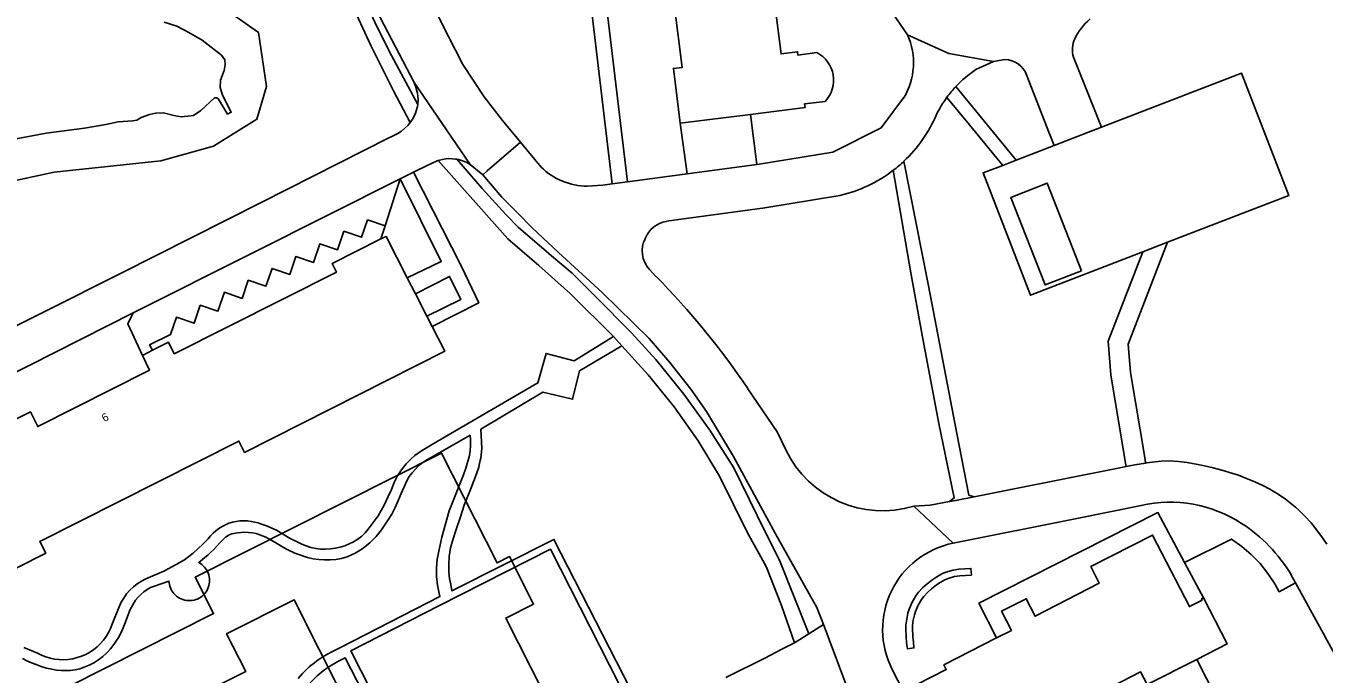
# Model space of a CAD drawing. Extents: x 158132 to 159658, y 385257 to 387209.
# Drawn here: x 159064.7 to 159226.8, y 386381.6 to 386462.6 of the extents above; entities that cross this region are included whole.
import ezdxf

# ---------------------------------------------------------------- set-up
doc = ezdxf.new("R2010")
doc.units = 0
for name, color, linetype in [('IMGEO_Groenvoorziening', 7, 'Continuous'), ('IMGEO_Meer_plas_ven_vijver', 7, 'Continuous'), ('IMGEO_Pand', 7, 'Continuous'), ('IMGEO_Pand_nummerreeks', 7, 'Continuous'), ('IMGEO_Pand_vergunning_verleend', 7, 'Continuous'), ('IMGEO_Parkeervlak_open', 7, 'Continuous'), ('IMGEO_Rijbaan_lokaal_gesloten', 7, 'Continuous'), ('IMGEO_Rijbaan_lokaal_open', 7, 'Continuous'), ('IMGEO_Voetpad_open', 7, 'Continuous')]:
    doc.layers.add(name, color=color, linetype=linetype)

msp = doc.modelspace()

# ---------------------------------------------------------------- linework, layer by layer
at = {"layer": 'IMGEO_Groenvoorziening'}
for points in [[(159088.96, 386465.12), (159093.72, 386461.76), (159094.7, 386455.04), (159093.51, 386450.93), (159088.09, 386447.57), (159081.49, 386445.73), (159068.17, 386444.32), (159059.08, 386442.37), (159042.9, 386435.88), (159037.76, 386432.56), (159020.21, 386419.95), (159017.17, 386418.5), (159014.2, 386417.9), (159011.48, 386417.94), (159008.93, 386418.79), (159006.56, 386420.41), (159001.86, 386425.64), (159000.77, 386428.72), (159000.8, 386431.97), (159002.13, 386435.24), (159005.17, 386440.01), (159011.8, 386444.98), (159020.33, 386450.04)], [(159109.52, 386437.62), (159109, 386435.97)]]:
    msp.add_lwpolyline(points, dxfattribs=at)
at = {"layer": 'IMGEO_Meer_plas_ven_vijver'}
msp.add_lwpolyline([(159081.92, 386463.07), (159083.53, 386462.57), (159085.02, 386461.77), (159086.68, 386460.82), (159088.16, 386459.66), (159089.1, 386458.94), (159089.5, 386458.35), (159089.55, 386457.77), (159089.41, 386457.01), (159088.96, 386455.8), (159088.92, 386454.9), (159089.23, 386453.96), (159090.31, 386451.8), (159089.86, 386451.58), (159088.73, 386453.44), (159088.49, 386453.63), (159088.22, 386453.61), (159086.52, 386452.04), (159085.6, 386451.41), (159084.87, 386451.31), (159084.07, 386451.25), (159083.15, 386451.41), (159081.84, 386451.74), (159080.84, 386451.69), (159080.1, 386451.52), (159079.07, 386451.14), (159078.52, 386450.8), (159078, 386450.75), (159076.16, 386450.61), (159074.66, 386450.28), (159071.97, 386449.81), (159067.17, 386449.18), (159061.17, 386448.08)], dxfattribs=at)
at = {"layer": 'IMGEO_Pand'}
for points in [[(159155.5, 386521.58), (159153.11, 386521.28), (159153.08, 386521.47), (159137.7, 386519.52), (159138.58, 386512.59), (159139.52, 386512.71), (159141.14, 386500), (159141.53, 386496.9), (159143.04, 386497.09), (159143.74, 386491.82), (159135.51, 386490.77), (159137.19, 386477.61), (159145.42, 386478.66), (159146.15, 386473.48), (159144.64, 386473.29), (159146.66, 386457.42), (159145.54, 386457.28), (159146.41, 386450.43)], [(159163.46, 386459.26), (159161.1, 386458.96), (159161.05, 386459.36), (159158.99, 386459.1), (159156.22, 386480.84), (159157.42, 386480.99), (159156.91, 386485.02), (159156.46, 386488.53), (159155.92, 386492.83), (159154.68, 386492.67), (159153.74, 386500), (159151.92, 386514.32), (159153.96, 386514.58), (159153.92, 386514.96), (159156.38, 386515.26)], [(159155.18, 386451.54), (159161.99, 386452.41), (159161.94, 386452.84), (159164.51, 386453.16)], [(159146.41, 386450.43), (159155.18, 386451.54)], [(159196.52, 386431.98), (159191.99, 386430.22), (159187.72, 386441.17), (159192.24, 386442.94), (159196.52, 386431.98)], [(159080.46, 386422.06), (159082.45, 386423.06), (159083.18, 386421.62), (159103.45, 386431.83), (159102.91, 386432.89), (159109, 386435.97)], [(159109, 386435.97), (159109.65, 386436.3), (159112.3, 386431.12)], [(159113.33, 386429.1), (159112.3, 386431.12)], [(159114.74, 386426.33), (159113.33, 386429.1)], [(159115.41, 386425.03), (159114.74, 386426.33)], [(159115.41, 386425.03), (159116.99, 386421.94), (159091.98, 386409.3), (159091.27, 386410.7), (159066.39, 386398.16), (159067.13, 386396.71), (159042.48, 386384.25), (159040.85, 386387.48)], [(159079.2, 386421.42), (159080.46, 386422.06)], [(159061.96, 386412.72), (159065.21, 386414.36), (159066.14, 386412.52), (159080.11, 386419.58), (159079.2, 386421.42)], [(159185.93, 386386.11), (159187.77, 386387.04), (159186.54, 386389.44), (159189.62, 386391), (159190.72, 386388.81), (159198.75, 386392.96), (159197.68, 386395.02), (159205.41, 386398.97), (159210.02, 386390.03), (159211.59, 386390.83), (159211.53, 386391.01), (159211.78, 386391.13)], [(159210.92, 386383.43), (159214.72, 386385.36), (159211.78, 386391.13)], [(159175.96, 386380.29), (159179.63, 386382.15), (159179.33, 386382.74), (159185.93, 386386.11)], [(159210.92, 386383.43), (159204.73, 386380.28), (159203.91, 386381.85), (159184.82, 386371.98), (159185.58, 386370.5), (159181.91, 386368.63)]]:
    msp.add_lwpolyline(points, dxfattribs=at)
msp.add_arc((159161.68, 386455.82), 3.88, 316.8175, 62.6095, dxfattribs=at)
at = {"layer": 'IMGEO_Pand_vergunning_verleend'}
msp.add_lwpolyline([(159050.57, 386368.04), (159057.32, 386371.44), (159056.43, 386373.19), (159088.1, 386389.15), (159085.8, 386393.7), (159116.59, 386409.22), (159123.52, 386395.49), (159125.08, 386396.27), (159128.07, 386390.33), (159124.61, 386388.59), (159130.93, 386376.07), (159110.74, 386365.89), (159098.15, 386390.88), (159089.73, 386386.63), (159092.11, 386381.91), (159085.18, 386378.43), (159091.59, 386365.71), (159079.32, 386359.4), (159081.2, 386355.82), (159075.09, 386353.07), (159074.31, 386354.62), (159060.77, 386347.79), (159050.57, 386368.04)], dxfattribs=at)
at = {"layer": 'IMGEO_Parkeervlak_open'}
for points in [[(159199.04, 386449.93), (159216.52, 386456.68), (159222.42, 386441.4), (159207.29, 386435.56)], [(159193.11, 386447.64), (159188.37, 386445.81)], [(159186.69, 386445.16), (159184.24, 386444.22), (159190.15, 386428.93), (159204.18, 386434.35)], [(159111.4, 386443.47), (159109.52, 386437.62)], [(159080.46, 386422.06), (159080.11, 386422.73), (159082.72, 386424.03), (159083.46, 386426.19), (159085.66, 386425.44), (159086.43, 386427.69), (159088.64, 386426.94), (159089.45, 386429.31), (159091.66, 386428.55), (159092.43, 386430.81), (159094.64, 386430.06), (159095.41, 386432.3), (159097.62, 386431.54), (159098.38, 386433.78), (159100.59, 386433.03), (159101.39, 386435.37), (159103.6, 386434.62), (159104.39, 386436.93), (159106.6, 386436.18), (159107.34, 386438.35), (159107.35, 386438.36), (159109.52, 386437.62)]]:
    msp.add_lwpolyline(points, dxfattribs=at)
at = {"layer": 'IMGEO_Rijbaan_lokaal_gesloten'}
for points in [[(159168.9, 386468.32), (159172.42, 386464.95), (159174.8, 386461.48)], [(159174.8, 386461.48), (159179.96, 386459.17), (159185.54, 386458.14)], [(159183.33, 386457.14), (159185.54, 386458.14)], [(159185.54, 386458.14), (159186.96, 386458.39)], [(159195.54, 386458.71), (159199.04, 386449.93)], [(159189.67, 386456.48), (159192.53, 386449.13), (159193.11, 386447.64)], [(159174.31, 386453.59), (159171.51, 386449.85), (159165.45, 386446.82), (159156.24, 386445.32), (159155.98, 386445.28)], [(159199.04, 386449.93), (159197.4, 386449.3), (159193.11, 386447.64)], [(159126.43, 386448.09), (159122.28, 386444.49), (159121.72, 386444)], [(159129.03, 386444.96), (159126.43, 386448.09)], [(159155.98, 386445.28), (159147.26, 386444.12)], [(159121.72, 386444), (159124.12, 386441.2), (159126.02, 386439.29), (159127.9, 386437.35), (159131.19, 386434.28), (159136.63, 386429.28), (159142.5, 386423.55), (159145.08, 386420.52), (159147.72, 386417.19), (159149.66, 386414.41), (159153.06, 386408.77), (159158.02, 386399.66), (159158.3, 386399.13), (159163.48, 386389.93), (159164.3, 386387.8)], [(159139.8, 386443.12), (159137.91, 386442.87)], [(159147.26, 386444.12), (159139.8, 386443.12)], [(159137.91, 386442.87), (159136.74, 386442.71), (159134.79, 386442.58)], [(159144.68, 386438.18), (159156.97, 386439.87), (159166.34, 386441.4)], [(159143.37, 386431.29), (159142.57, 386432.17)], [(159159.6, 386409.6), (159158.5, 386411.85), (159154.85, 386417.26)], [(159180.51, 386397.96), (159175.58, 386402.58)], [(159160.68, 386385.48), (159162.48, 386386.63)], [(159162.48, 386386.63), (159164.3, 386387.8)], [(159164.3, 386387.8), (159168.14, 386377.56)], [(159160.68, 386385.48), (159159.1, 386384.71), (159156.98, 386383.59), (159152.1, 386381.17)], [(159174.28, 386379.43), (159172.88, 386382.17)]]:
    msp.add_lwpolyline(points, dxfattribs=at)
for centre, radius, start, end in [((159202.49, 386457.69), 7.56, 130.1649, 154.13), ((159166.99, 386458.01), 8.55, 328.8485, 23.9455), ((159198.44, 386459.66), 3.05, 154.2235, 198.2419), ((159186.87, 386455.39), 3, 21.3107, 88.289), ((159191.34, 386445.19), 14.39, 123.8165, 136.9206), ((159191.41, 386445.14), 14.47, 136.9878, 143.8973), ((159191.35, 386445.2), 14.4, 143.9376, 153.9311), ((159162.42, 386458.35), 17.39, 313.3149, 336.8992), ((159134.78, 386450.73), 8.15, 225.1221, 270.0585), ((159162.38, 386458.39), 17.45, 307.5493, 313.3359), ((159162.41, 386458.34), 17.39, 283.0538, 307.5485), ((159145.18, 386434.85), 3.36, 98.6958, 159.2412), ((159144.93, 386434.47), 3.29, 151.3825, 224.3061), ((159073.64, 386362.54), 97.93, 33.976, 44.593), ((159171.67, 386415.39), 13.39, 205.6112, 286.9345), ((159182.68, 386387.17), 11, 101.3473, 207.0455)]:
    msp.add_arc(centre, radius, start, end, dxfattribs=at)
at = {"layer": 'IMGEO_Rijbaan_lokaal_open'}
for points in [[(159113.14, 386455.52), (159108.94, 386463.56), (159106.64, 386468.87), (159104.74, 386473.72), (159103.08, 386479.14)], [(159109.67, 386479.93), (159110.05, 386478.53), (159111.67, 386473.93), (159114, 386468.46), (159116.52, 386463.07), (159119.22, 386457.77), (159121.92, 386453.72), (159124.19, 386450.76), (159126.43, 386448.09)], [(159120.17, 386445.26), (159113.14, 386455.52)], [(159113.14, 386455.52), (159113.35, 386454.95), (159113.51, 386454.48), (159113.56, 386454.21), (159113.61, 386453.88), (159113.67, 386453.37), (159113.63, 386452.88), (159113.61, 386452.78)], [(159113.61, 386452.78), (159113.58, 386452.52), (159113.47, 386452.1), (159113.33, 386451.7), (159113.16, 386451.3), (159112.95, 386450.93), (159112.67, 386450.53)], [(159057.35, 386422.06), (159076.55, 386431.69), (159094.11, 386440.59), (159110.07, 386448.64), (159110.2, 386448.7), (159111.12, 386449.17), (159111.56, 386449.46), (159111.98, 386449.8), (159112.36, 386450.17), (159112.67, 386450.53)], [(159113.09, 386444.32), (159114.87, 386445.21), (159115.95, 386445.69), (159116.05, 386445.73), (159116.15, 386445.76)], [(159116.15, 386445.76), (159116.33, 386445.82), (159116.71, 386445.92), (159117.11, 386445.98), (159117.51, 386446.01), (159117.91, 386446), (159118.31, 386445.96), (159118.49, 386445.93)], [(159118.49, 386445.93), (159118.59, 386445.91), (159118.7, 386445.89), (159119.09, 386445.78), (159119.46, 386445.64), (159119.82, 386445.47), (159120.17, 386445.26)], [(159121.72, 386444), (159120.17, 386445.26)], [(159078.04, 386426.72), (159093.07, 386434.3), (159111.4, 386443.47)], [(159111.4, 386443.47), (159113.09, 386444.32)], [(159061.77, 386418.51), (159078.04, 386426.72)], [(159202.11, 386407.52), (159200.89, 386407.28), (159187.68, 386404.66), (159183.1, 386403.74)], [(159204.54, 386407.96), (159203.19, 386407.73), (159202.11, 386407.52)], [(159204.54, 386407.96), (159204.71, 386407.98), (159205.36, 386408.08), (159206.46, 386408.19), (159207.52, 386408.23), (159208.65, 386408.17), (159209.74, 386408.03), (159211.07, 386407.78), (159211.9, 386407.61), (159212.97, 386407.36), (159214.04, 386407.08), (159215.43, 386406.66), (159216.13, 386406.43), (159217.16, 386406.05), (159218.18, 386405.62), (159219.18, 386405.16), (159220.07, 386404.69), (159221.09, 386404.08), (159222, 386403.46), (159223.28, 386402.45), (159223.7, 386402.07), (159224.49, 386401.3), (159225.23, 386400.48), (159225.69, 386399.92), (159226.65, 386398.61), (159227.16, 386397.82)], [(159175.58, 386402.58), (159177.61, 386402.68), (159180.04, 386403.14)], [(159183.1, 386403.74), (159180.78, 386403.27), (159180.04, 386403.14)], [(159180.51, 386397.96), (159195.93, 386401.05), (159203.97, 386402.67)], [(159222.7, 386394.02), (159223.26, 386393)], [(159223.26, 386393), (159236, 386369.77)]]:
    msp.add_lwpolyline(points, dxfattribs=at)
for centre, radius, start, end in [((159207.6, 386386.79), 16.29, 56.7454, 102.8562), ((159205.89, 386383.96), 19.6, 30.8976, 57.1149)]:
    msp.add_arc(centre, radius, start, end, dxfattribs=at)
at = {"layer": 'IMGEO_Voetpad_open'}
for points in [[(159139.8, 386443.12), (159130.94, 386517.43)], [(159112.67, 386450.53), (159110.57, 386454.48), (159107.78, 386460.06), (159105.15, 386465.72), (159102.7, 386471.45), (159101.94, 386473.64), (159099.08, 386483.66), (159095.79, 386495.63)], [(159137.91, 386442.87), (159133.51, 386479.83), (159133.13, 386479.84), (159132.76, 386479.89), (159132.39, 386479.96), (159132.04, 386480.08), (159131.69, 386480.22), (159131.36, 386480.39), (159131.05, 386480.59), (159130.75, 386480.82), (159130.48, 386481.08), (159130.23, 386481.35), (159130.01, 386481.66), (159129.81, 386481.98), (159129.64, 386482.31), (159109.67, 386479.93)], [(159103.08, 386479.14), (159102.22, 386478.95), (159104.26, 386472.38), (159106.78, 386466.27), (159108.25, 386463.08), (159110.04, 386459.45), (159113.61, 386452.78)], [(159180.83, 386455.02), (159188.37, 386445.81)], [(159186.69, 386445.16), (159182.54, 386450.22), (159179.71, 386453.67)], [(159155.98, 386445.28), (159155.18, 386451.54)], [(159146.41, 386450.43), (159147.26, 386444.12)], [(159116.15, 386445.76), (159124.87, 386435.99), (159128.73, 386432.67), (159132.68, 386429.11), (159138.05, 386423.77)], [(159162.48, 386386.63), (159158.89, 386395.6), (159156.01, 386401.41), (159153.08, 386407.38), (159150.09, 386412.07), (159146.84, 386416.59), (159143.34, 386420.92), (159140.3, 386424.26), (159135.82, 386428.79), (159132.89, 386431.69), (159130.31, 386433.87), (159129.98, 386434.15), (159126.16, 386437.44), (159124.62, 386439.03), (159121.65, 386442.26), (159118.49, 386445.93)], [(159183.1, 386403.74), (159182.45, 386403.97), (159180.96, 386411.67), (159177.42, 386430.11), (159174.35, 386445.69)], [(159188.37, 386445.81), (159186.69, 386445.16)], [(159112.3, 386431.12), (159116.54, 386433.17), (159111.4, 386443.47)], [(159113.09, 386444.32), (159119.08, 386432.55), (159121.23, 386428), (159115.41, 386425.03)], [(159180.04, 386403.14), (159180.63, 386403.6), (159178.71, 386412.89), (159176.69, 386423.48), (159175.2, 386431.73), (159173.01, 386444.55)], [(159207.29, 386435.56), (159202.35, 386422.83), (159202.64, 386419.3), (159204.47, 386408.4), (159204.54, 386407.96)], [(159204.18, 386434.35), (159207.29, 386435.56)], [(159202.11, 386407.52), (159202.04, 386407.94), (159201.92, 386408.71), (159200.19, 386418.99), (159199.84, 386423.2), (159204.18, 386434.35)], [(159114.74, 386426.33), (159118.97, 386428.4), (159117.58, 386431.3), (159113.33, 386429.1)], [(159078.04, 386426.72), (159077.37, 386425.36), (159079.2, 386421.42)], [(159064.39, 386384.92), (159066.1, 386384.21), (159066.61, 386383.96), (159067.14, 386383.75), (159067.69, 386383.59), (159068.24, 386383.47), (159068.81, 386383.41), (159069.38, 386383.39), (159069.95, 386383.43), (159070.51, 386383.51), (159071.07, 386383.65), (159071.61, 386383.83), (159072.13, 386384.05), (159072.63, 386384.33), (159073.11, 386384.64), (159073.55, 386385), (159073.97, 386385.39), (159074.34, 386385.82), (159074.68, 386386.28), (159074.98, 386386.77), (159075.23, 386387.28), (159075.44, 386387.81), (159076.3, 386390), (159076.56, 386390.56), (159076.87, 386391.09), (159077.23, 386391.6), (159077.64, 386392.06), (159078.08, 386392.49), (159078.56, 386392.88), (159079.08, 386393.22), (159079.62, 386393.51), (159081.87, 386394.47), (159083.43, 386395.27), (159084.48, 386395.87), (159085.55, 386396.72), (159086.77, 386397.83), (159087.42, 386398.48), (159087.71, 386398.85), (159088.03, 386399.2), (159088.38, 386399.51), (159088.76, 386399.79), (159089.16, 386400.04), (159089.58, 386400.25), (159090.02, 386400.43), (159090.46, 386400.57), (159090.93, 386400.67), (159091.39, 386400.73), (159091.86, 386400.75), (159092.33, 386400.73), (159092.8, 386400.67), (159093.26, 386400.57), (159093.68, 386400.48), (159094.09, 386400.34), (159094.71, 386400.11), (159095.96, 386399.56), (159097.66, 386398.52), (159098.56, 386398.1), (159099.11, 386397.82), (159099.68, 386397.6), (159100.26, 386397.42), (159100.86, 386397.29), (159101.47, 386397.22), (159102.08, 386397.2), (159102.7, 386397.23), (159103.3, 386397.31), (159103.9, 386397.44), (159104.49, 386397.62), (159105.05, 386397.85), (159105.6, 386398.13), (159106.12, 386398.45), (159106.61, 386398.82), (159107.04, 386399.25), (159107.41, 386399.7), (159107.92, 386400.36), (159108.66, 386401.36), (159109.42, 386402.72), (159109.93, 386403.79), (159110.31, 386404.65), (159110.55, 386405.21), (159110.65, 386405.53), (159111.07, 386406.35), (159111.57, 386407.12), (159112.14, 386407.85), (159112.78, 386408.51), (159113.23, 386408.92), (159113.95, 386409.41), (159115.12, 386410.12), (159116.76, 386411.07), (159128.6, 386417.97), (159129.63, 386421.66), (159133.16, 386420.73), (159138.05, 386423.77)], [(159138.05, 386423.77), (159139.11, 386422.6)], [(159140.13, 386379.79), (159130.62, 386398.42), (159117.87, 386391.99), (159117.73, 386392.77), (159117.59, 386393.53), (159117.47, 386394.31), (159117.48, 386395.28), (159117.54, 386396.3), (159117.71, 386397.35), (159117.98, 386398.36), (159118.36, 386399.54), (159118.95, 386401.26), (159119.42, 386402.7), (159120.29, 386404.87), (159120.94, 386406.6), (159121.23, 386407.44), (159121.34, 386407.9), (159121.42, 386408.28), (159121.48, 386408.59), (159121.55, 386408.95), (159121.59, 386409.42), (159121.61, 386409.78), (159121.47, 386412.18), (159129.24, 386416.83), (159132.95, 386415.93), (159133.82, 386419.51), (159139.11, 386422.6)], [(159139.11, 386422.6), (159142.39, 386419.01), (159145.65, 386414.99), (159148.62, 386410.76), (159151.3, 386406.33), (159154.78, 386399.32), (159157.15, 386395.04), (159159.06, 386390.17), (159160.68, 386385.48)], [(159086.99, 386396.15), (159087.37, 386396.46), (159087.73, 386396.78), (159088.08, 386397.11), (159088.47, 386397.53), (159088.86, 386397.95), (159089.26, 386398.36), (159089.42, 386398.53), (159089.59, 386398.68), (159089.78, 386398.81), (159089.98, 386398.93), (159090.19, 386399.03), (159090.4, 386399.11), (159090.62, 386399.17), (159090.85, 386399.21), (159091.08, 386399.23), (159091.55, 386399.29), (159092.02, 386399.32), (159092.48, 386399.3), (159092.95, 386399.24), (159093.41, 386399.15), (159093.86, 386399.01), (159094.3, 386398.84), (159094.61, 386398.68), (159094.92, 386398.55), (159095.77, 386398.06), (159096.62, 386397.53), (159097.3, 386397.16), (159098.27, 386396.72), (159099.85, 386396.17), (159100.55, 386396.01), (159101.25, 386395.9), (159101.96, 386395.85), (159102.68, 386395.86), (159103.39, 386395.93), (159104.09, 386396.05), (159104.78, 386396.23), (159105.79, 386396.72), (159106.63, 386397.21), (159107.63, 386397.98), (159108.43, 386398.78), (159109.07, 386399.6), (159109.83, 386400.73), (159110.35, 386401.58), (159110.8, 386402.42), (159111.2, 386403.35), (159111.54, 386404.16), (159112.23, 386405.75), (159112.55, 386406.27), (159112.91, 386406.76), (159113.32, 386407.22), (159113.76, 386407.64), (159114.23, 386408.03), (159114.74, 386408.37), (159115.27, 386408.67), (159120.14, 386411.44), (159120.18, 386410.9), (159120.19, 386410.22), (159120.14, 386409.45), (159120.04, 386408.76), (159119.8, 386407.9), (159119.62, 386407.32), (159119.32, 386406.49), (159117.55, 386402), (159116.62, 386398.72), (159116.24, 386396.96), (159116.05, 386395.91), (159115.95, 386394.85), (159115.95, 386393.77), (159116.06, 386392.71), (159116.27, 386391.66), (159116.38, 386391.27), (159103.95, 386384.91), (159103.06, 386384.44), (159102.25, 386384.05), (159101.55, 386383.62), (159101.01, 386383.25), (159100.69, 386383), (159100.09, 386382.52), (159099.79, 386382.23), (159099.19, 386381.65), (159098.65, 386381.04)], [(159185.93, 386386.11), (159183.72, 386390.45), (159206.07, 386401.77), (159209.41, 386395.55)], [(159209.41, 386395.55), (159215.26, 386398.46), (159216.54, 386397.55), (159217.73, 386396.52), (159218.83, 386395.39), (159219.81, 386394.17), (159220.68, 386392.86), (159221.22, 386391.88), (159223.26, 386393)], [(159064.23, 386383.53), (159064.79, 386383.25), (159065.36, 386382.99), (159065.95, 386382.77), (159066.58, 386382.53), (159067.23, 386382.34), (159067.89, 386382.2), (159068.47, 386382.09), (159069.05, 386382.03), (159069.64, 386382.02), (159070.23, 386382.05), (159070.81, 386382.13), (159071.38, 386382.26), (159071.94, 386382.44), (159072.57, 386382.7), (159073.16, 386383.01), (159073.73, 386383.37), (159074.26, 386383.78), (159074.76, 386384.24), (159075.21, 386384.74), (159075.62, 386385.27), (159076.29, 386386.3), (159076.73, 386387.18), (159077.05, 386387.99), (159077.33, 386388.78), (159077.7, 386389.65), (159078.19, 386390.55), (159078.35, 386390.83), (159078.67, 386391.21), (159079.02, 386391.55), (159079.4, 386391.87), (159079.81, 386392.15), (159080.24, 386392.39), (159080.7, 386392.59), (159082.52, 386393.21), (159082.6, 386392.8), (159082.64, 386392.59), (159082.71, 386392.38), (159082.8, 386392.18), (159082.9, 386391.99), (159083.02, 386391.81), (159083.15, 386391.64), (159083.31, 386391.48), (159083.47, 386391.34), (159083.65, 386391.21), (159083.85, 386391.09), (159084.06, 386390.98), (159084.27, 386390.9), (159084.5, 386390.84), (159084.73, 386390.79), (159084.96, 386390.77), (159085.19, 386390.77), (159085.43, 386390.79), (159085.66, 386390.83), (159085.88, 386390.89), (159086.1, 386390.97), (159086.3, 386391.07), (159086.49, 386391.19), (159086.67, 386391.33), (159086.84, 386391.48), (159086.99, 386391.65), (159087.13, 386391.82), (159087.25, 386392.01), (159087.35, 386392.22), (159087.44, 386392.42), (159087.5, 386392.64), (159087.55, 386392.86), (159087.58, 386393.08), (159087.58, 386393.31), (159087.57, 386393.53), (159087.54, 386393.76), (159087.49, 386393.98), (159087.42, 386394.19), (159087.33, 386394.4), (159087.22, 386394.6), (159087.1, 386394.78), (159086.96, 386394.96), (159086.8, 386395.12), (159086.63, 386395.27), (159086.45, 386395.4), (159086.25, 386395.52), (159086.72, 386395.92), (159086.99, 386396.15)], [(159116.34, 386390.14), (159130.18, 386397.22), (159138.81, 386380.26), (159113.88, 386367.55), (159105.26, 386384.48), (159116.34, 386390.14)], [(159182.77, 386393.96), (159182.02, 386393.93), (159181.32, 386393.87), (159180.66, 386393.77), (159179.88, 386393.55), (159179.46, 386393.37), (159178.88, 386393.05), (159178.43, 386392.74), (159177.77, 386392.23), (159177.27, 386391.78), (159176.82, 386391.29), (159176.54, 386390.91), (159176.11, 386390.2), (159175.79, 386389.43), (159175.65, 386388.98), (159175.51, 386388.33), (159175.43, 386387.65), (159175.42, 386387.32), (159175.45, 386386.29), (159175.52, 386385.58), (159175.6, 386384.85), (159174.77, 386384.76), (159174.68, 386385.49), (159174.61, 386386.23), (159174.58, 386387.33), (159174.6, 386387.72), (159174.69, 386388.46), (159174.84, 386389.19), (159175, 386389.72), (159175.37, 386390.58), (159175.84, 386391.38), (159176.18, 386391.82), (159176.68, 386392.37), (159177.23, 386392.87), (159177.94, 386393.42), (159178.44, 386393.76), (159179.09, 386394.12), (159179.6, 386394.34), (159180.49, 386394.59), (159181.22, 386394.7), (159181.97, 386394.76), (159182.72, 386394.8), (159182.77, 386393.96)], [(159211.78, 386391.13), (159209.41, 386395.55)], [(159080.78, 386345.29), (159079.09, 386348.8), (159088.64, 386353.63), (159085.52, 386359.69), (159090.21, 386362.31), (159091.04, 386362.97), (159091.82, 386363.69), (159092.52, 386364.48), (159093.16, 386365.33), (159093.72, 386366.23), (159094.2, 386367.17), (159097.37, 386375.13), (159098.21, 386377.35), (159099, 386378.98), (159099.6, 386379.83), (159100.28, 386380.63), (159101.03, 386381.37), (159101.83, 386382.04), (159102.7, 386382.64), (159103.61, 386383.16), (159104.56, 386383.6), (159113.49, 386366.21), (159128.77, 386373.97), (159130.51, 386370.43)], [(159214.42, 386376.55), (159210.92, 386383.43)]]:
    msp.add_lwpolyline(points, dxfattribs=at)

# ---------------------------------------------------------------- texts
at = {"layer": 'IMGEO_Pand_nummerreeks'}
msp.add_text('6', height=1, rotation=27.1525, dxfattribs=at).set_placement((159074.44, 386413.07))

doc.saveas('drawing.dxf')
